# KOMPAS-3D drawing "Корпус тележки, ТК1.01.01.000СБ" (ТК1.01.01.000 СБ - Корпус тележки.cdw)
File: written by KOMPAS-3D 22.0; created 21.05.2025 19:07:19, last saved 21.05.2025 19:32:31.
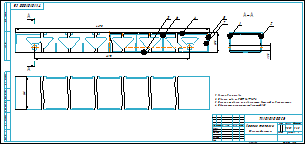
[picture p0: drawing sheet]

Sheet 1: A4x3, landscape

Document properties: Автор: user; Масса: 95.511296; Форматы листов документа: A4@4~3; Полное имя файла: ..\Корпус тележки.a3d

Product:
- Part/product: Корпус тележки  | designation ТК1.01.01.000СБ
    Масса: 95.511296
    Форматы листов документа: A4@4~3
    source file: ТК1.01.01.000 - Корпус тележки.spw
  - Component [detail]: Стенка боковая  | designation ТК1.01.01.001-01  | qty 1  | pos. 2  | Масса: 11.528421; source file: ..\Стенка боковая.cdw, ..\Стенка боковая.m3d, Стенка боковая.cdw
  - Component [detail]: Стенка боковая  | designation ТК1.01.01.001  | qty 1  | pos. 1  | Масса: 11.51708; source file: ..\Стенка боковая.cdw, ..\Стенка боковая.m3d, Стенка боковая.cdw
  - Component [detail]: Ребро продольное  | designation ТК1.01.01.004  | qty 2  | pos. 5  | Масса: 0.575358; source file: ..\Ребро продольное.cdw, ..\Ребро продольное.m3d, Чертеж Ребро продольное.cdw
  - Component [detail]: Ребро продольное  | designation ТК1.01.01.004-01  | qty 5  | pos. 6  | Масса: 0.574941; source file: ..\Ребро продольное _ -01.cdw, ..\Ребро продольное.cdw, ..\Ребро продольное.m3d, Чертеж Ребро продольное.cdw
  - Component [detail]: Верхняя пластина  | designation ТК1.01.01.003  | qty 1  | pos. 4  | Масса: 41.469866; Форматы листов документа: A4@4~3; source file: ..\Верхняя пластина.cdw, ..\Верхняя пластина.m3d, Верхняя пластина.cdw
  - Component [detail]: Пластина нижняя  | designation ТК1.01.01.002  | qty 1  | pos. 3  | Масса: 26.939167; Форматы листов документа: A3; source file: ..\Корпус тележки\КД\ТК1.01.01.002 - Пластина нижняя.cdw, ..\Корпус тележки\Пластина нижняя.cdw, ..\Пластина нижняя.m3d, ТК1.01.01.002 - Пластина нижняя.cdw
  - Component [standard]: Гайка М12-6H(S18) ГОСТ 5915-70  | qty 2  | pos. 7  | Масса: 0.01567; Раздел спецификации: Стандартные изделия; Рассекать на разрезах: no; additional columns: М12-6H (S18)

Title block, sheet 1: Наименование: Корпус тележки / Сборочный чертеж; Масса: 95,51; Количество листов документа: 1; Форматы листов документа: A4 3; stored path: D:\Работа\2025\5. Май\Задание №6 - Тележка для крыши\3Д\Тележка в сборе\Корпус тележки\КД\ТК1.01.01.000 СБ - Корпус тележки.cdw

Views: Вид 1, Местный разрез 1, Слева, Разрез А-А, Проекционный вид 3
Referenced files in D:\Работа\2025\5. Май\Задание №6 - Тележка для крыши\3Д\Тележка в сборе\Корпус тележки\: Верхняя пластина.m3d, Пластина нижняя.m3d, Ребро продольное.m3d, Корпус тележки.a3d, Стенка боковая.m3d, Верхняя пластина.cdw, Ребро продольное _ -01.cdw, Ребро продольное.cdw, Стенка боковая.cdw
Referenced files in D:\Работа\2025\5. Май\Задание №6 - Тележка для крыши\3Д\Тележка в сборе\Корпус тележки\КД\: Верхняя пластина.cdw, Чертеж Ребро продольное.cdw, ТК1.01.01.002 - Пластина нижняя.cdw, Стенка боковая.cdw
Referenced files in D:\Работа\2025\5. Май\Задание №6 - Тележка для крыши\3Д\Тележка в сборе\Корпус тележки\Корпус тележки\: Пластина нижняя.cdw
Referenced files in D:\Работа\2025\5. Май\Задание №6 - Тележка для крыши\3Д\Тележка в сборе\Корпус тележки\Корпус тележки\КД\: ТК1.01.01.002 - Пластина нижняя.cdw
Referenced files in D:\Program Files\ASCON\KOMPAS-3D v22\Libs\PolynomLib\DATA\vault\Methods\Kompas\3D\: PLib_Nut_OST92_900.m3d
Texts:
  ТК1.01.01.000
  ТК1.01.01.003
  Верхняя пластина
  ТК1.01.01.004 - 01
  ТК1.01.01.004 - 01
  Ребро продольное
  ТК1.01.01.002
  Пластина нижняя
  Гайка М12-6H(S18) ГОСТ 5915-70
  Крепежное изделие ГОСТ
  Гайка
  ГОСТ
  BOSimple***PART:26b7db98-4be1-8179-e7df-2046e24e1536***SHORTLOC:Root±30±10±20±©{}110±10±50±60[Нет;Без покрытия;Без указания материала;-;12;1,75;18]
  ТК1.01.01.004
  ТК1.01.01.001 - 01
  ТК1.01.01.001 - 01
  Стенка боковая
  ТК1.01.01.001
  ТК1.01.01.001-01 Стенка боковая
  ТК1.01.01.001 Стенка боковая
  ТК1.01.01.004 Ребро продольное
  ТК1.01.01.004-01 Ребро продольное
  ТК1.01.01.003 Верхняя пластина
  ТК1.01.01.002 Пластина нижняя
  ТК1.01.01.000
  ТК1.01.01.000 СБ Корпус тележки
Dimensions and other numbers on the sheet: 4470; 105; 4270; 5; 4; 7; 6; 3; 0; 2; 25; 1; 168; 58; 40Х; 1:2,5; 95,51; 01

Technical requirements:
  Размры для справок.
  Сварные швы по ГОСТ 14771-76.
  Брызги от сварки на поверхности деталей не допускаются.
  Обеспечить соосность отверстий ∅25.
